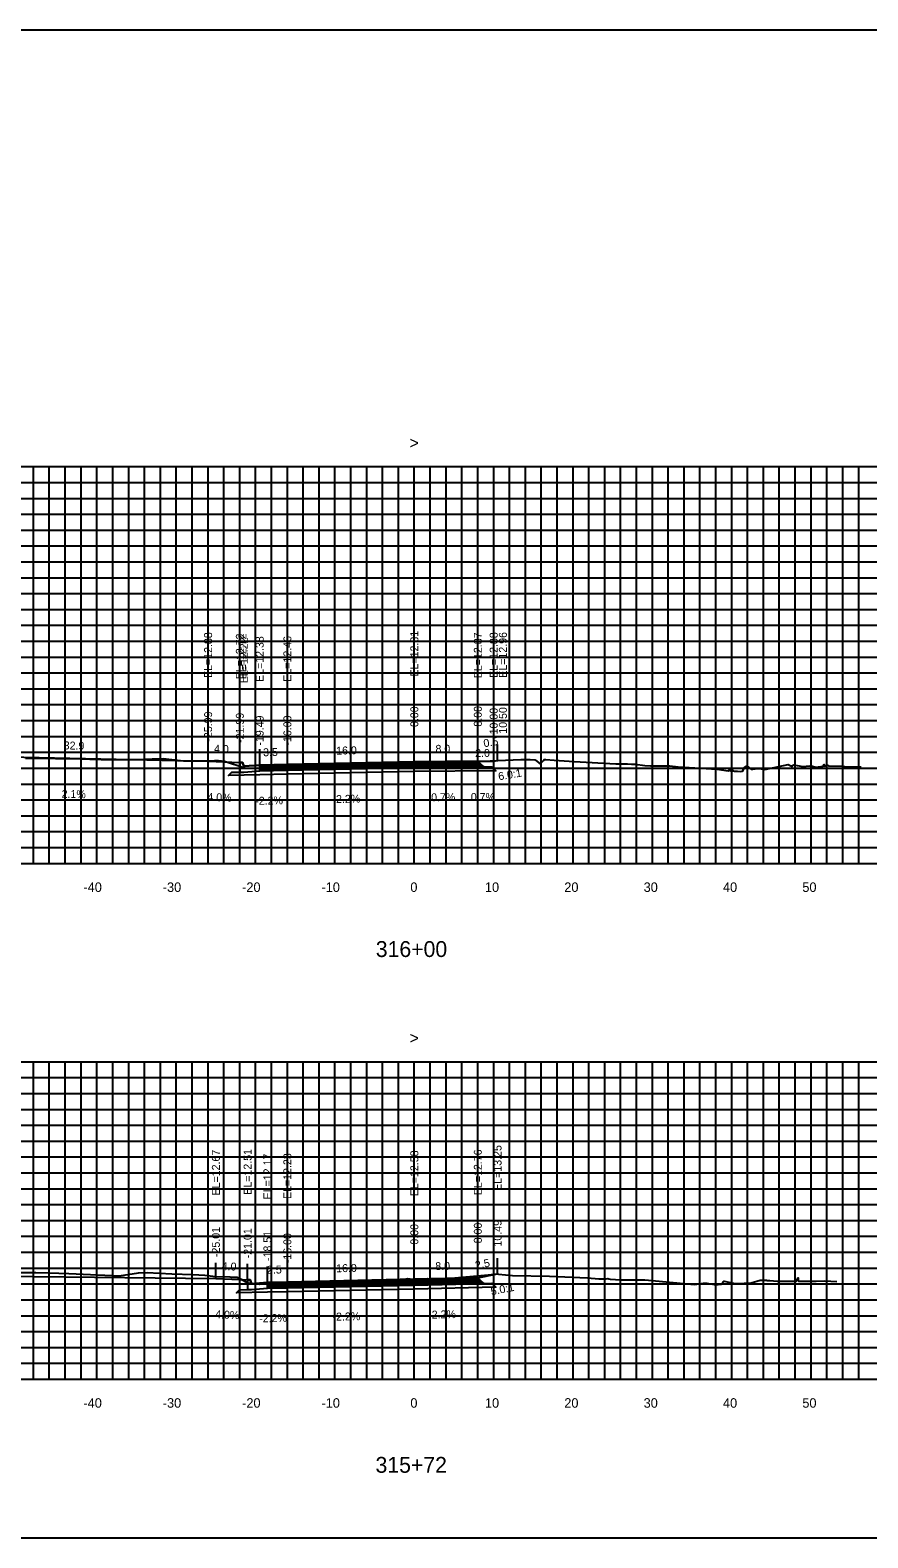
# Model space of a CAD drawing. Extents: x 1797652 to 1804145, y 245981 to 250269.
# Drawn here: x 1802242.6 to 1802348.2, y 250079.4 to 250269.4 of the extents above; entities that cross this region are included whole.
import ezdxf

# ---------------------------------------------------------------- set-up
doc = ezdxf.new("R2010")
doc.units = 0
for name, color, linetype in [('1', 7, 'Continuous'), ('10', 7, 'Continuous'), ('3', 7, 'Continuous'), ('4', 7, 'Continuous'), ('60', 7, 'Continuous'), ('BASE', 7, 'Continuous'), ('CL-CNST', 7, 'Continuous'), ('Level 62', 7, 'Continuous'), ('LOWER BINDER', 7, 'Continuous'), ('M-ROADS', 7, 'Continuous'), ('UPPER BINDER', 7, 'Continuous'), ('WEARING', 7, 'Continuous')]:
    doc.layers.add(name, color=color, linetype=linetype)

msp = doc.modelspace()

# ---------------------------------------------------------------- linework, layer by layer
for p, q in [((1802265.01, 250177.32), (1802265.01, 250179.32)), ((1802269.01, 250177.16), (1802269.01, 250179.16)), ((1802271.51, 250176.82), (1802271.51, 250178.82)), ((1802275, 250176.89), (1802275, 250178.89)), ((1802291, 250177.24), (1802291, 250179.24)), ((1802299, 250177.3), (1802299, 250179.3)), ((1802301, 250177.31), (1802301, 250179.31)), ((1802301.5, 250177.4), (1802301.5, 250179.4)), ((1802265.99, 250112.11), (1802265.99, 250114.11)), ((1802299, 250112.19), (1802299, 250114.19)), ((1802301.49, 250112.69), (1802301.49, 250114.69)), ((1802269.99, 250111.95), (1802269.99, 250113.95)), ((1802272.49, 250111.61), (1802272.49, 250113.61)), ((1802275, 250111.66), (1802275, 250113.66)), ((1802291, 250112.01), (1802291, 250114.01))]:
    msp.add_line(p, q)
for points in [[(1802141, 250079.43), (1802441, 250079.43), (1802441, 250269.43), (1802141, 250269.43)], [(1802271.51, 250176.82), (1802269.51, 250176.66), (1802269.34, 250177.16), (1802269.01, 250177.16), (1802269.01, 250175.93), (1802269.51, 250175.93), (1802271.51, 250176.1)], [(1802272.49, 250111.61), (1802270.49, 250111.45), (1802270.32, 250111.95), (1802269.99, 250111.95), (1802269.98, 250110.73), (1802270.48, 250110.73), (1802272.49, 250110.89)]]:
    msp.add_lwpolyline(points, close=True)
at = {"layer": '60'}
for p, q in [((1802141, 250164.43), (1802441, 250164.43)), ((1802251, 250164.37), (1802251, 250164.43)), ((1802261, 250164.37), (1802261, 250164.43)), ((1802271, 250164.37), (1802271, 250164.43)), ((1802281, 250164.37), (1802281, 250164.43)), ((1802291, 250164.37), (1802291, 250164.43)), ((1802301, 250164.37), (1802301, 250164.43)), ((1802311, 250164.37), (1802311, 250164.43)), ((1802321, 250164.37), (1802321, 250164.43)), ((1802331, 250164.37), (1802331, 250164.43)), ((1802341, 250164.37), (1802341, 250164.43)), ((1802141, 250099.43), (1802441, 250099.43)), ((1802251, 250099.37), (1802251, 250099.43)), ((1802261, 250099.37), (1802261, 250099.43)), ((1802271, 250099.37), (1802271, 250099.43)), ((1802281, 250099.37), (1802281, 250099.43)), ((1802291, 250099.37), (1802291, 250099.43)), ((1802301, 250099.37), (1802301, 250099.43)), ((1802311, 250099.37), (1802311, 250099.43)), ((1802321, 250099.37), (1802321, 250099.43)), ((1802331, 250099.37), (1802331, 250099.43)), ((1802341, 250099.37), (1802341, 250099.43))]:
    msp.add_line(p, q, dxfattribs=at)
at = {"layer": 'BASE'}
for points in [[(1802271.51, 250176.1), (1802275, 250176.17), (1802291, 250176.52), (1802299.75, 250176.59), (1802300.75, 250176.59), (1802301.27, 250176.1), (1802291, 250176.02), (1802275, 250175.67), (1802271.51, 250175.6), (1802267.6, 250175.51), (1802268.01, 250175.91), (1802269.01, 250175.93), (1802269.51, 250175.93)], [(1802272.49, 250110.89), (1802275, 250110.94), (1802291, 250111.29), (1802299.75, 250111.49), (1802300.75, 250111.51), (1802301.27, 250111.02), (1802291, 250110.79), (1802275, 250110.44), (1802272.49, 250110.39), (1802268.58, 250110.3), (1802268.98, 250110.7), (1802269.98, 250110.73), (1802270.48, 250110.73)]]:
    msp.add_lwpolyline(points, close=True, dxfattribs=at)
at = {"layer": 'CL-CNST'}
for points in [[(1802221.11, 250176.26), (1802225.11, 250176.26), (1802232.1, 250178.01), (1802265.01, 250177.32), (1802269.01, 250177.16), (1802269.34, 250177.16), (1802269.51, 250176.66), (1802271.51, 250176.82), (1802275, 250176.89), (1802291, 250177.24), (1802299, 250177.3), (1802301, 250177.31), (1802301.5, 250177.4)], [(1802207.05, 250113.27), (1802209.73, 250111.52), (1802213.73, 250111.52), (1802216.26, 250112.65), (1802265.99, 250112.11), (1802269.99, 250111.95), (1802270.32, 250111.95), (1802270.49, 250111.45), (1802272.49, 250111.61), (1802275, 250111.66), (1802291, 250112.01), (1802299, 250112.19), (1802301.49, 250112.69)]]:
    msp.add_lwpolyline(points, dxfattribs=at)
at = {"layer": 'Level 62'}
for p, q in [((1802141, 250214.43), (1802441, 250214.43)), ((1802243, 250164.43), (1802243, 250214.43)), ((1802245, 250164.43), (1802245, 250214.43)), ((1802247, 250164.43), (1802247, 250214.43)), ((1802249, 250164.43), (1802249, 250214.43)), ((1802251, 250164.43), (1802251, 250214.43)), ((1802253, 250164.43), (1802253, 250214.43)), ((1802255, 250164.43), (1802255, 250214.43)), ((1802257, 250164.43), (1802257, 250214.43)), ((1802259, 250164.43), (1802259, 250214.43)), ((1802261, 250164.43), (1802261, 250214.43)), ((1802263, 250164.43), (1802263, 250214.43)), ((1802265, 250164.43), (1802265, 250214.43)), ((1802267, 250164.43), (1802267, 250214.43)), ((1802269, 250164.43), (1802269, 250214.43)), ((1802271, 250164.43), (1802271, 250214.43)), ((1802273, 250164.43), (1802273, 250214.43)), ((1802275, 250164.43), (1802275, 250214.43)), ((1802277, 250164.43), (1802277, 250214.43)), ((1802279, 250164.43), (1802279, 250214.43)), ((1802281, 250164.43), (1802281, 250214.43)), ((1802283, 250164.43), (1802283, 250214.43)), ((1802285, 250164.43), (1802285, 250214.43)), ((1802287, 250164.43), (1802287, 250214.43)), ((1802289, 250164.43), (1802289, 250214.43)), ((1802291, 250164.43), (1802291, 250214.43)), ((1802293, 250164.43), (1802293, 250214.43)), ((1802295, 250164.43), (1802295, 250214.43)), ((1802297, 250164.43), (1802297, 250214.43)), ((1802299, 250164.43), (1802299, 250214.43)), ((1802301, 250164.43), (1802301, 250214.43)), ((1802303, 250164.43), (1802303, 250214.43)), ((1802305, 250164.43), (1802305, 250214.43)), ((1802307, 250164.43), (1802307, 250214.43)), ((1802309, 250164.43), (1802309, 250214.43)), ((1802311, 250164.43), (1802311, 250214.43)), ((1802313, 250164.43), (1802313, 250214.43)), ((1802315, 250164.43), (1802315, 250214.43)), ((1802317, 250164.43), (1802317, 250214.43)), ((1802319, 250164.43), (1802319, 250214.43)), ((1802321, 250164.43), (1802321, 250214.43)), ((1802323, 250164.43), (1802323, 250214.43)), ((1802325, 250164.43), (1802325, 250214.43)), ((1802327, 250164.43), (1802327, 250214.43)), ((1802329, 250164.43), (1802329, 250214.43)), ((1802331, 250164.43), (1802331, 250214.43)), ((1802333, 250164.43), (1802333, 250214.43)), ((1802335, 250164.43), (1802335, 250214.43)), ((1802337, 250164.43), (1802337, 250214.43)), ((1802339, 250164.43), (1802339, 250214.43)), ((1802341, 250164.43), (1802341, 250214.43)), ((1802343, 250164.43), (1802343, 250214.43)), ((1802345, 250164.43), (1802345, 250214.43)), ((1802347, 250164.43), (1802347, 250214.43)), ((1802141, 250212.43), (1802441, 250212.43)), ((1802141, 250210.43), (1802441, 250210.43)), ((1802141, 250208.43), (1802441, 250208.43)), ((1802141, 250206.43), (1802441, 250206.43)), ((1802141, 250204.43), (1802441, 250204.43)), ((1802141, 250202.43), (1802441, 250202.43)), ((1802141, 250200.43), (1802441, 250200.43)), ((1802141, 250198.43), (1802441, 250198.43)), ((1802141, 250196.43), (1802441, 250196.43)), ((1802141, 250194.43), (1802441, 250194.43)), ((1802141, 250192.43), (1802441, 250192.43)), ((1802141, 250190.43), (1802441, 250190.43)), ((1802141, 250188.43), (1802441, 250188.43)), ((1802141, 250186.43), (1802441, 250186.43)), ((1802141, 250184.43), (1802441, 250184.43)), ((1802141, 250182.43), (1802441, 250182.43)), ((1802141, 250180.43), (1802441, 250180.43)), ((1802141, 250178.43), (1802441, 250178.43)), ((1802141, 250176.43), (1802441, 250176.43)), ((1802141, 250174.43), (1802441, 250174.43)), ((1802141, 250172.43), (1802441, 250172.43)), ((1802141, 250170.43), (1802441, 250170.43)), ((1802141, 250168.43), (1802441, 250168.43)), ((1802141, 250166.43), (1802441, 250166.43)), ((1802141, 250164.43), (1802441, 250164.43)), ((1802141, 250139.43), (1802441, 250139.43)), ((1802243, 250099.43), (1802243, 250139.43)), ((1802245, 250099.43), (1802245, 250139.43)), ((1802247, 250099.43), (1802247, 250139.43)), ((1802249, 250099.43), (1802249, 250139.43)), ((1802251, 250099.43), (1802251, 250139.43)), ((1802253, 250099.43), (1802253, 250139.43)), ((1802255, 250099.43), (1802255, 250139.43)), ((1802257, 250099.43), (1802257, 250139.43)), ((1802259, 250099.43), (1802259, 250139.43)), ((1802261, 250099.43), (1802261, 250139.43)), ((1802263, 250099.43), (1802263, 250139.43)), ((1802265, 250099.43), (1802265, 250139.43)), ((1802267, 250099.43), (1802267, 250139.43)), ((1802269, 250099.43), (1802269, 250139.43)), ((1802271, 250099.43), (1802271, 250139.43)), ((1802273, 250099.43), (1802273, 250139.43)), ((1802275, 250099.43), (1802275, 250139.43)), ((1802277, 250099.43), (1802277, 250139.43)), ((1802279, 250099.43), (1802279, 250139.43)), ((1802281, 250099.43), (1802281, 250139.43)), ((1802283, 250099.43), (1802283, 250139.43)), ((1802285, 250099.43), (1802285, 250139.43)), ((1802287, 250099.43), (1802287, 250139.43)), ((1802289, 250099.43), (1802289, 250139.43)), ((1802291, 250099.43), (1802291, 250139.43)), ((1802293, 250099.43), (1802293, 250139.43)), ((1802295, 250099.43), (1802295, 250139.43)), ((1802297, 250099.43), (1802297, 250139.43)), ((1802299, 250099.43), (1802299, 250139.43)), ((1802301, 250099.43), (1802301, 250139.43)), ((1802303, 250099.43), (1802303, 250139.43)), ((1802305, 250099.43), (1802305, 250139.43)), ((1802307, 250099.43), (1802307, 250139.43)), ((1802309, 250099.43), (1802309, 250139.43)), ((1802311, 250099.43), (1802311, 250139.43)), ((1802313, 250099.43), (1802313, 250139.43)), ((1802315, 250099.43), (1802315, 250139.43)), ((1802317, 250099.43), (1802317, 250139.43)), ((1802319, 250099.43), (1802319, 250139.43)), ((1802321, 250099.43), (1802321, 250139.43)), ((1802323, 250099.43), (1802323, 250139.43)), ((1802325, 250099.43), (1802325, 250139.43)), ((1802327, 250099.43), (1802327, 250139.43)), ((1802329, 250099.43), (1802329, 250139.43)), ((1802331, 250099.43), (1802331, 250139.43)), ((1802333, 250099.43), (1802333, 250139.43)), ((1802335, 250099.43), (1802335, 250139.43)), ((1802337, 250099.43), (1802337, 250139.43)), ((1802339, 250099.43), (1802339, 250139.43)), ((1802341, 250099.43), (1802341, 250139.43)), ((1802343, 250099.43), (1802343, 250139.43)), ((1802345, 250099.43), (1802345, 250139.43)), ((1802347, 250099.43), (1802347, 250139.43)), ((1802141, 250137.43), (1802441, 250137.43)), ((1802141, 250135.43), (1802441, 250135.43)), ((1802141, 250133.43), (1802441, 250133.43)), ((1802141, 250131.43), (1802441, 250131.43)), ((1802141, 250129.43), (1802441, 250129.43)), ((1802141, 250127.43), (1802441, 250127.43)), ((1802141, 250125.43), (1802441, 250125.43)), ((1802141, 250123.43), (1802441, 250123.43)), ((1802141, 250121.43), (1802441, 250121.43)), ((1802141, 250119.43), (1802441, 250119.43)), ((1802141, 250117.43), (1802441, 250117.43)), ((1802141, 250115.43), (1802441, 250115.43)), ((1802141, 250113.43), (1802441, 250113.43)), ((1802141, 250111.43), (1802441, 250111.43)), ((1802141, 250109.43), (1802441, 250109.43)), ((1802141, 250107.43), (1802441, 250107.43)), ((1802141, 250105.43), (1802441, 250105.43)), ((1802141, 250103.43), (1802441, 250103.43)), ((1802141, 250101.43), (1802441, 250101.43)), ((1802141, 250099.43), (1802441, 250099.43))]:
    msp.add_line(p, q, dxfattribs=at)
at = {"layer": 'LOWER BINDER'}
for points in [[(1802275, 250176.55), (1802291, 250176.9), (1802299.36, 250176.96), (1802299.55, 250176.77), (1802291, 250176.71), (1802275, 250176.36), (1802271.51, 250176.29), (1802271.51, 250176.48)], [(1802275, 250176.36), (1802291, 250176.71), (1802299.55, 250176.77), (1802299.75, 250176.59), (1802291, 250176.52), (1802275, 250176.17), (1802271.51, 250176.1), (1802271.51, 250176.29)], [(1802275, 250111.32), (1802291, 250111.67), (1802299.36, 250111.86), (1802299.55, 250111.67), (1802291, 250111.48), (1802275, 250111.13), (1802272.49, 250111.08), (1802272.49, 250111.27)], [(1802275, 250111.13), (1802291, 250111.48), (1802299.55, 250111.67), (1802299.75, 250111.49), (1802291, 250111.29), (1802275, 250110.94), (1802272.49, 250110.89), (1802272.49, 250111.08)]]:
    msp.add_lwpolyline(points, close=True, dxfattribs=at)
at = {"layer": 'M-ROADS'}
for points in [[(1802242, 250177.69), (1802243.29, 250177.69), (1802245.77, 250177.63), (1802246.86, 250177.63), (1802247.89, 250177.63), (1802250.12, 250177.56), (1802251.53, 250177.52), (1802255.87, 250177.51), (1802257.97, 250177.62), (1802259.36, 250177.63), (1802260.45, 250177.51), (1802261.9, 250177.35), (1802265.55, 250177.37), (1802265.83, 250177.4), (1802266.06, 250177.4), (1802266.3, 250177.4), (1802267.09, 250177.32), (1802269.65, 250176.47), (1802269.67, 250176.41), (1802269.72, 250176.42), (1802271.24, 250176.49), (1802272.06, 250176.42), (1802272.21, 250176.43), (1802272.5, 250176.47), (1802273.09, 250176.49), (1802273.75, 250176.5), (1802274.34, 250176.44), (1802274.72, 250176.42), (1802274.94, 250176.43), (1802276.24, 250176.49), (1802282.75, 250176.63), (1802288.7, 250176.77), (1802289.27, 250176.8), (1802289.95, 250176.83), (1802290.85, 250176.8), (1802291.2, 250176.78), (1802291.84, 250176.81), (1802292.45, 250176.83), (1802292.82, 250176.79), (1802293.44, 250176.93), (1802294.18, 250177.01), (1802294.43, 250177.02), (1802294.94, 250176.83), (1802295.41, 250176.9), (1802299.58, 250177.31), (1802304.42, 250177.53), (1802304.76, 250177.53), (1802305.23, 250177.53), (1802305.47, 250177.53), (1802305.59, 250177.54), (1802306.21, 250177.47), (1802306.31, 250177.42), (1802306.41, 250177.35), (1802306.73, 250177.04), (1802306.76, 250177.04), (1802306.86, 250176.96), (1802307.28, 250177.38), (1802307.37, 250177.53), (1802307.58, 250177.53), (1802308.63, 250177.45), (1802311.16, 250177.28), (1802316.38, 250176.96), (1802317.87, 250176.96), (1802318.35, 250176.93), (1802318.48, 250176.95), (1802318.56, 250176.93), (1802318.82, 250176.94), (1802320.04, 250176.75), (1802320.75, 250176.71), (1802323.09, 250176.71), (1802323.22, 250176.71), (1802324.26, 250176.58), (1802326.35, 250176.46), (1802329.15, 250176.29), (1802330.54, 250176.1), (1802330.78, 250176.2), (1802330.8, 250176.11), (1802331.05, 250176.14), (1802331.07, 250176.24), (1802331.13, 250176.11), (1802331.14, 250176.09), (1802331.16, 250176.08), (1802331.21, 250176.08), (1802331.35, 250176.07), (1802331.45, 250176.06), (1802331.73, 250176.04), (1802332.09, 250176.01), (1802332.35, 250176.04), (1802332.37, 250176.04), (1802332.66, 250176.54), (1802332.86, 250176.7), (1802332.9, 250176.5), (1802332.94, 250176.67), (1802333.48, 250176.26), (1802333.55, 250176.29), (1802333.64, 250176.32), (1802333.94, 250176.36), (1802334.48, 250176.39), (1802335.16, 250176.24), (1802338.13, 250176.9), (1802338.61, 250176.62), (1802338.66, 250176.76), (1802338.73, 250176.82), (1802338.84, 250176.83), (1802339.91, 250176.64), (1802340.86, 250176.71), (1802340.99, 250176.69), (1802341.17, 250176.67), (1802341.6, 250176.56), (1802342.53, 250176.67), (1802342.66, 250176.91), (1802342.67, 250176.73), (1802342.68, 250176.67), (1802343.05, 250176.79), (1802343.2, 250176.73), (1802345.01, 250176.7), (1802345.41, 250176.6), (1802347.31, 250176.59)], [(1802241.21, 250112.87), (1802243.32, 250112.85), (1802244.93, 250112.83), (1802247.46, 250112.75), (1802253.79, 250112.45), (1802256.22, 250112.83), (1802257.35, 250112.85), (1802260.45, 250112.72), (1802263.07, 250112.61), (1802264.58, 250112.55), (1802265.93, 250112.38), (1802267.74, 250112.34), (1802267.91, 250112.3), (1802268.69, 250112.3), (1802269.18, 250112.01), (1802269.99, 250111.58), (1802271.48, 250111.42), (1802271.52, 250111.42), (1802271.52, 250111.41), (1802271.55, 250111.42), (1802272.01, 250111.49), (1802272.56, 250111.58), (1802272.61, 250111.58), (1802273.81, 250111.62), (1802273.84, 250111.62), (1802274.99, 250111.57), (1802275.74, 250111.59), (1802276.24, 250111.61), (1802278.67, 250111.67), (1802281.44, 250111.74), (1802286.75, 250111.87), (1802287.25, 250111.89), (1802288.54, 250111.95), (1802288.94, 250111.96), (1802289.99, 250112.09), (1802290.19, 250112.12), (1802290.47, 250112.07), (1802290.99, 250112.01), (1802291.47, 250111.95), (1802291.89, 250112), (1802292.72, 250112.12), (1802293.08, 250112.08), (1802293.94, 250111.96), (1802294.9, 250112.07), (1802295.19, 250112.12), (1802300.29, 250112.58), (1802301.39, 250112.71), (1802301.59, 250112.66), (1802303.38, 250112.51), (1802308.05, 250112.4), (1802312.82, 250112.2), (1802314.24, 250112.07), (1802314.58, 250112.07), (1802314.75, 250112.09), (1802315.1, 250112.07), (1802315.14, 250112.07), (1802315.16, 250112.07), (1802315.37, 250112.1), (1802315.5, 250112.06), (1802315.53, 250112.06), (1802315.66, 250112.04), (1802317.03, 250111.96), (1802318.78, 250111.96), (1802320.04, 250111.93), (1802326.29, 250111.35), (1802327.46, 250111.53), (1802327.86, 250111.53), (1802328.09, 250111.5), (1802328.32, 250111.44), (1802329.03, 250111.31), (1802329.08, 250111.33), (1802329.25, 250111.34), (1802329.27, 250111.33), (1802329.28, 250111.34), (1802329.7, 250111.41), (1802329.92, 250111.71), (1802330.05, 250111.79), (1802331.01, 250111.57), (1802331.47, 250111.5), (1802331.66, 250111.49), (1802333.46, 250111.57), (1802334.57, 250111.9), (1802335.38, 250111.89), (1802335.48, 250111.88), (1802335.5, 250111.87), (1802335.53, 250111.86), (1802335.58, 250111.86), (1802335.71, 250111.86), (1802335.81, 250111.86), (1802336.71, 250111.78), (1802339.01, 250111.78), (1802339.04, 250111.78), (1802339.15, 250111.79), (1802339.15, 250111.81), (1802339.37, 250112.19), (1802339.38, 250111.88), (1802339.4, 250111.77), (1802339.43, 250111.77), (1802339.52, 250111.77), (1802339.54, 250111.77), (1802339.57, 250111.77), (1802340.46, 250111.77), (1802340.81, 250111.77), (1802341, 250111.77), (1802341.53, 250111.78), (1802341.64, 250111.79), (1802342.75, 250111.82), (1802344.26, 250111.73)]]:
    msp.add_lwpolyline(points, dxfattribs=at)
at = {"layer": 'UPPER BINDER'}
for points in [[(1802299.36, 250176.96), (1802299.16, 250177.15), (1802291, 250177.09), (1802275, 250176.74), (1802271.51, 250176.67), (1802271.51, 250176.48), (1802275, 250176.55), (1802291, 250176.9)], [(1802299.36, 250111.86), (1802299.16, 250112.04), (1802291, 250111.86), (1802275, 250111.51), (1802272.49, 250111.46), (1802272.49, 250111.27), (1802275, 250111.32), (1802291, 250111.67)]]:
    msp.add_lwpolyline(points, close=True, dxfattribs=at)
at = {"layer": 'WEARING'}
for points in [[(1802299.16, 250177.15), (1802299, 250177.3), (1802291, 250177.24), (1802275, 250176.89), (1802271.51, 250176.82), (1802271.51, 250176.67), (1802275, 250176.74), (1802291, 250177.09)], [(1802299.16, 250112.04), (1802299, 250112.19), (1802291, 250112.01), (1802275, 250111.66), (1802272.49, 250111.61), (1802272.49, 250111.46), (1802275, 250111.51), (1802291, 250111.86)]]:
    msp.add_lwpolyline(points, close=True, dxfattribs=at)

# ---------------------------------------------------------------- texts
for s, rotation, p in [('6.0:1', 9.4623, (1802301.66, 250174.89)), ('5.0:1', 11.3099, (1802300.73, 250109.99))]:
    msp.add_text(s, height=1, rotation=rotation).set_placement(p)
at = {"layer": '1'}
for s, p in [('316+00', (1802286.14, 250152.63)), ('315+72', (1802286.11, 250087.63))]:
    msp.add_text(s, height=2, dxfattribs=at).set_placement(p)
at = {"layer": '10'}
for s, p in [('-40', (1802249.3, 250160.83)), ('-30', (1802259.3, 250160.83)), ('-20', (1802269.3, 250160.83)), ('-10', (1802279.3, 250160.83)), ('0', (1802290.5, 250160.83)), ('10', (1802299.9, 250160.83)), ('20', (1802309.9, 250160.83)), ('30', (1802319.9, 250160.83)), ('40', (1802329.9, 250160.83)), ('50', (1802339.9, 250160.83)), ('-40', (1802249.3, 250095.83)), ('-30', (1802259.3, 250095.83)), ('-20', (1802269.3, 250095.83)), ('-10', (1802279.3, 250095.83)), ('0', (1802290.5, 250095.83)), ('10', (1802299.9, 250095.83)), ('20', (1802309.9, 250095.83)), ('30', (1802319.9, 250095.83)), ('40', (1802329.9, 250095.83)), ('50', (1802339.9, 250095.83))]:
    msp.add_text(s, height=1.2, dxfattribs=at).set_placement(p)
at = {"layer": '3'}
for s, p in [('EL=12.88', (1802265.51, 250187.79)), ('EL=12.72', (1802269.51, 250187.63)), ('EL=12.72', (1802269.84, 250187.63)), ('EL=12.22', (1802270.01, 250187.13)), ('EL=12.38', (1802272.01, 250187.29)), ('EL=12.46', (1802275.5, 250187.32)), ('EL=12.81', (1802291.5, 250187.97)), ('EL=12.87', (1802299.5, 250187.77)), ('EL=12.88', (1802301.5, 250187.79)), ('EL=12.96', (1802302.66, 250187.82)), ('-25.99', (1802265.51, 250179.77)), ('-21.99', (1802269.51, 250179.61)), ('-19.49', (1802272.01, 250179.27)), ('-16.00', (1802275.5, 250179.27)), ('0.00', (1802291.5, 250181.61)), ('8.00', (1802299.5, 250181.66)), ('10.00', (1802301.5, 250180.68)), ('10.50', (1802302.66, 250180.77)), ('EL=12.67', (1802266.49, 250122.58)), ('EL=12.51', (1802270.49, 250122.67)), ('EL=12.17', (1802272.99, 250122.08)), ('EL=12.23', (1802275.5, 250122.13)), ('EL=12.58', (1802291.5, 250122.49)), ('EL=12.76', (1802299.5, 250122.62)), ('EL=13.25', (1802301.99, 250123.16)), ('-25.01', (1802266.49, 250114.82)), ('-21.01', (1802270.49, 250114.66)), ('-18.51', (1802272.99, 250114.32)), ('0.00', (1802291.5, 250116.38)), ('8.00', (1802299.5, 250116.55)), ('10.49', (1802301.99, 250116.14)), ('-16.00', (1802275.5, 250114.04))]:
    msp.add_text(s, height=1, rotation=90, dxfattribs=at).set_placement(p)
at = {"layer": '4'}
for s, rotation, p in [('32.9', 358.7947, (1802246.8, 250178.8)), ('4.0', 357.7094, (1802265.74, 250178.39)), ('3.5', 1.2603, (1802271.95, 250177.93)), ('16.0', 1.2603, (1802281.16, 250178.13)), ('8.0', 0.3956, (1802293.67, 250178.36)), ('2.0', 0.3956, (1802298.67, 250177.83)), ('0.5', 9.4623, (1802299.8, 250179.06)), ('2.1%', 358.7947, (1802246.54, 250172.7)), ('4.0%', 357.7094, (1802264.9, 250172.32)), ('-2.2%', 1.2603, (1802280.7, 250172.02)), ('0.7%', 0.3956, (1802293.12, 250172.26)), ('0.7%', 0.3956, (1802298.12, 250172.29)), ('-2.2%', 1.2603, (1802270.96, 250171.8)), ('4.0', 357.7094, (1802266.71, 250113.18)), ('8.0', 1.2603, (1802293.65, 250113.17)), ('2.5', 11.3099, (1802298.77, 250113.27)), ('2.5', 1.2603, (1802272.44, 250112.71)), ('16.0', 1.2603, (1802281.16, 250112.9)), ('4.0%', 357.7094, (1802265.88, 250107.11)), ('-2.2%', 1.2603, (1802271.45, 250106.58)), ('-2.2%', 1.2603, (1802280.7, 250106.79)), ('2.2%', 1.2603, (1802293.2, 250107.06))]:
    msp.add_text(s, height=1, rotation=rotation, dxfattribs=at).set_placement(p)
at = {"layer": '60'}
for p in [(1802290.39, 250216.68), (1802290.39, 250141.68)]:
    msp.add_text('>', height=1.5, dxfattribs=at).set_placement(p)

doc.saveas('drawing.dxf')
